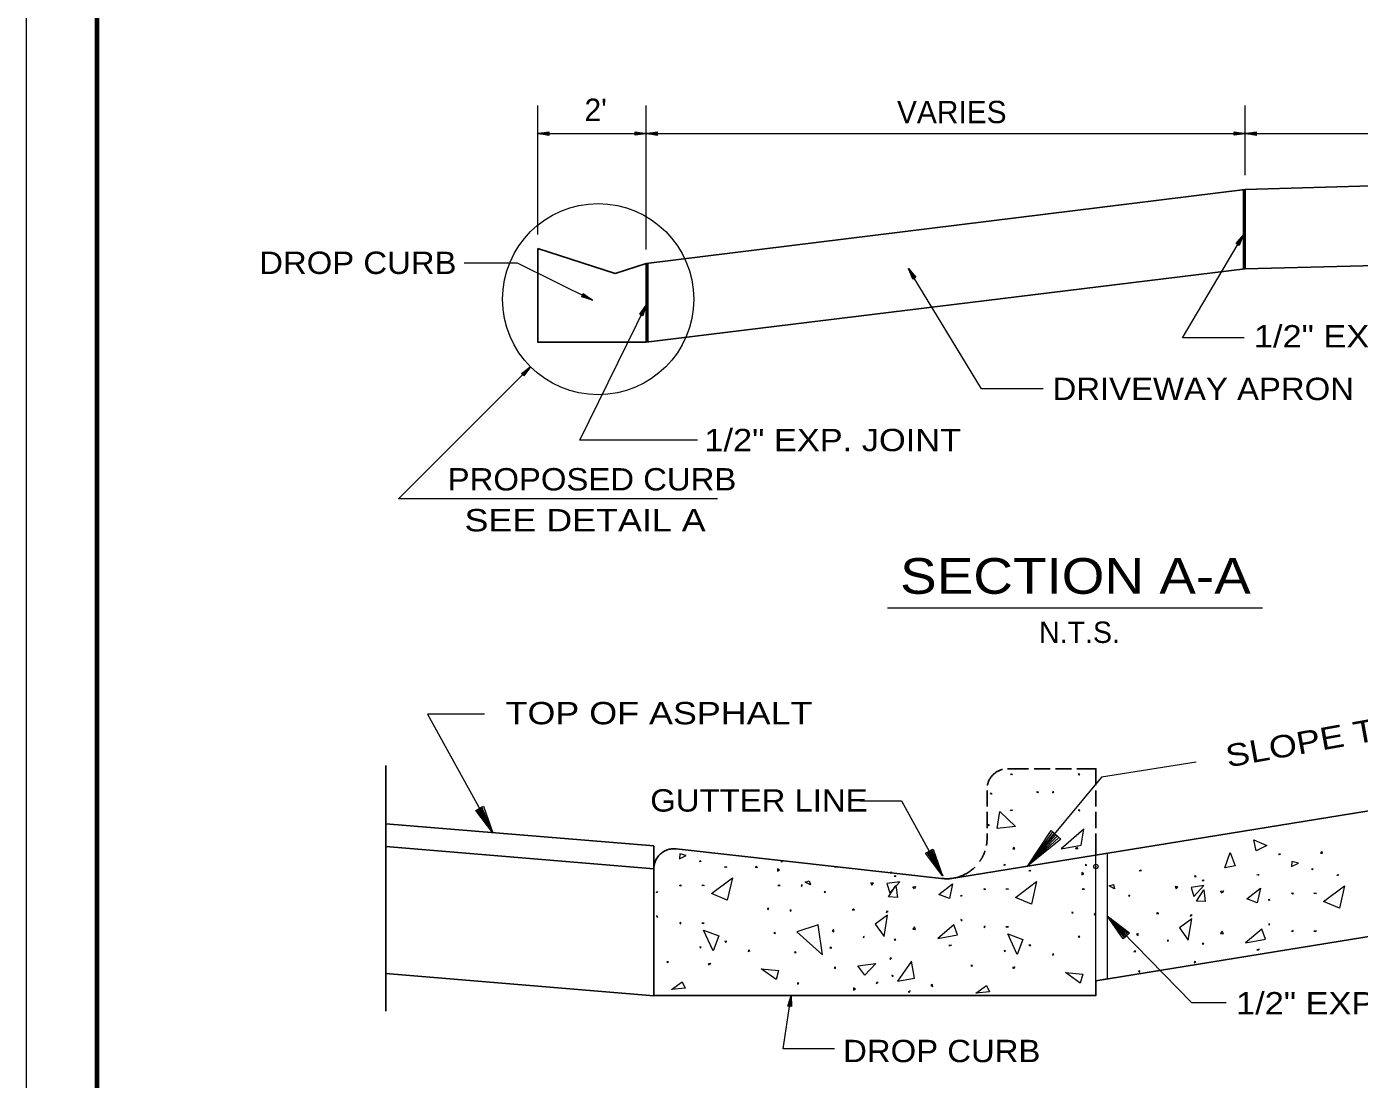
# Model space of a CAD drawing. Extents: x 124.7 to 141.7, y -6.7 to 4.3.
# Drawn here: x 124.656 to 129.626, y -4.341 to -0.415 of the extents above; entities that cross this region are included whole.
import ezdxf

# ---------------------------------------------------------------- set-up
doc = ezdxf.new("R2010")
doc.units = 0
doc.header["$LTSCALE"] = 0.033
doc.header["$PDMODE"] = 32
doc.header["$PDSIZE"] = 0.0165
for name, color, linetype, lineweight in [('6', 7, 'Continuous', 13), ('60', 7, 'Continuous', 13), ('7', 7, 'Continuous', 13), ('8', 7, 'Continuous', 13)]:
    doc.layers.add(name, color=color, linetype=linetype, lineweight=lineweight)

msp = doc.modelspace()

# ---------------------------------------------------------------- linework, layer by layer
at = {"layer": '6'}
for p, q in [((126.56211, -1.19092), (126.56211, -0.70965)), ((126.96649, -1.24615), (126.96649, -0.70965)), ((129.20005, -0.96993), (129.20005, -0.70965)), ((126.56211, -0.81446), (126.96649, -0.81446)), ((126.96649, -0.81446), (129.20005, -0.81446)), ((129.20005, -0.81446), (130.22682, -0.81446)), ((128.68544, -3.53976), (128.68564, -3.53974))]:
    msp.add_line(p, q, dxfattribs=at)
at = {"layer": '6', "lineweight": 25}
for p, q in [((129.1938, -1.31883), (129.1938, -1.0231)), ((129.20005, -1.02234), (129.20005, -1.31806)), ((126.96649, -1.29853), (126.96649, -1.59245)), ((126.97237, -1.59173), (126.97237, -1.29781)), ((125.99551, -3.17074), (125.99551, -4.08672)), ((128.09045, -3.59451), (130.92926, -3.13361)), ((128.31326, -3.18331), (128.3927, -3.18331)), ((128.4127, -3.18331), (128.4727, -3.18331)), ((128.4927, -3.18331), (128.5527, -3.18331)), ((128.23764, -3.32402), (128.23764, -3.26402)), ((128.64341, -3.26402), (128.64341, -3.32402)), ((128.23764, -3.40402), (128.23764, -3.34402)), ((128.64341, -3.34402), (128.64341, -3.40402)), ((125.99551, -3.38868), (126.99492, -3.47056)), ((128.23764, -3.44185), (128.23764, -3.42402)), ((128.64341, -3.42402), (128.64341, -3.50473)), ((125.99551, -3.47346), (126.99492, -3.55649)), ((127.07894, -3.48168), (128.09045, -3.59451)), ((128.64341, -3.97384), (131.48223, -3.51295)), ((126.99492, -4.03), (125.99551, -3.94698))]:
    msp.add_line(p, q, dxfattribs=at)
for points in [[(130.22682, -0.99256), (129.20005, -1.02234), (126.96649, -1.29853), (126.85148, -1.33557), (126.56211, -1.24331)], [(126.56211, -1.24331), (126.56211, -1.59245), (126.96649, -1.59245)], [(130.22682, -1.29244), (129.20005, -1.31806), (126.96649, -1.59245)], [(128.29489, -3.18557), (128.29205, -3.18634), (128.28925, -3.18722), (128.28648, -3.18821), (128.28375, -3.1893), (128.28106, -3.1905), (128.27844, -3.1918), (128.27585, -3.19321), (128.27332, -3.19471), (128.27086, -3.19631), (128.26846, -3.198), (128.26612, -3.19979), (128.26386, -3.20167), (128.26168, -3.20362), (128.25956, -3.20568), (128.25754, -3.2078), (128.25559, -3.21), (128.25374, -3.21228), (128.25197, -3.21462), (128.25029, -3.21704), (128.24871, -3.21952), (128.24723, -3.22206), (128.24584, -3.22465), (128.24456, -3.22729), (128.24339, -3.22999), (128.24231, -3.23273), (128.24135, -3.2355), (128.2405, -3.23831), (128.23975, -3.24116), (128.23911, -3.24402), (128.23911, -3.24402)], [(128.5727, -3.18331), (128.64341, -3.18331), (128.64341, -3.24402)], [(128.64341, -3.97384), (128.64341, -4.02829), (128.64341, -3.97384), (128.64341, -4.02829), (126.99492, -4.02829), (126.99492, -3.4723)], [(128.2351, -3.4694), (128.23527, -3.46846), (128.23544, -3.46751), (128.23559, -3.46657), (128.23575, -3.46564), (128.2359, -3.46469), (128.23604, -3.46374), (128.23618, -3.4628), (128.2363, -3.46185), (128.23643, -3.46091), (128.23654, -3.45996), (128.23666, -3.45901), (128.23676, -3.45806), (128.23686, -3.45711), (128.23696, -3.45616), (128.23704, -3.45521), (128.23712, -3.45426), (128.2372, -3.4533), (128.23727, -3.45235), (128.23733, -3.4514), (128.23739, -3.45045), (128.23744, -3.44949), (128.23748, -3.44854), (128.23752, -3.44758), (128.23755, -3.44664), (128.23758, -3.44568), (128.2376, -3.44472), (128.23761, -3.44377), (128.23763, -3.44281), (128.23764, -3.44185)], [(127.07893, -3.48168), (127.07456, -3.48131), (127.07018, -3.48121), (127.06579, -3.48135), (127.06143, -3.48176), (127.05709, -3.48242), (127.0528, -3.48332), (127.04857, -3.48447), (127.04442, -3.48586), (127.04034, -3.4875), (127.03637, -3.48936), (127.03252, -3.49146), (127.02879, -3.49378), (127.02521, -3.4963), (127.02178, -3.49903), (127.01851, -3.50196), (127.01542, -3.50506), (127.01251, -3.50834), (127.0098, -3.51179), (127.00729, -3.51539), (127.00499, -3.51912), (127.00292, -3.52299), (127.00107, -3.52697), (126.99946, -3.53104), (126.99808, -3.53521), (126.99695, -3.53945), (126.99606, -3.54374), (126.99543, -3.54808), (126.99505, -3.55245), (126.99493, -3.55683), (126.99493, -3.55683)], [(128.2096, -3.52956), (128.2105, -3.52829), (128.21139, -3.52701), (128.21226, -3.52572), (128.21311, -3.52442), (128.21396, -3.5231), (128.21479, -3.52178), (128.2156, -3.52046), (128.21641, -3.51912), (128.2172, -3.51777), (128.21797, -3.51643), (128.21874, -3.51506), (128.21948, -3.5137), (128.22022, -3.51232), (128.22094, -3.51094), (128.22164, -3.50954), (128.22233, -3.50815), (128.22301, -3.50674), (128.22367, -3.50533), (128.22431, -3.50392), (128.22495, -3.50249), (128.22556, -3.50106), (128.22617, -3.49962), (128.22675, -3.49818), (128.22732, -3.49673), (128.22789, -3.49527), (128.22843, -3.49381), (128.22896, -3.49234), (128.22947, -3.49087), (128.22997, -3.4894), (128.22997, -3.4894)], [(128.06961, -3.59218), (128.07423, -3.59261), (128.07886, -3.59292), (128.0835, -3.59308), (128.08814, -3.59309), (128.09277, -3.59297), (128.09741, -3.59271), (128.10202, -3.59229), (128.10663, -3.59175), (128.11122, -3.59105), (128.11578, -3.59022), (128.12031, -3.58925), (128.12481, -3.58815), (128.12928, -3.5869), (128.13371, -3.58551), (128.13809, -3.58399), (128.14243, -3.58234), (128.14671, -3.58055), (128.15094, -3.57865), (128.15509, -3.57659), (128.1592, -3.57443), (128.16323, -3.57214), (128.16719, -3.56972), (128.17106, -3.56718), (128.17487, -3.56452), (128.17859, -3.56175), (128.18222, -3.55886), (128.18577, -3.55587), (128.18922, -3.55277), (128.19256, -3.54956), (128.19256, -3.54956)]]:
    msp.add_lwpolyline(points, dxfattribs=at)
at = {"layer": '6'}
for points in [[(129.19658, -1.57594), (128.96645, -1.57594), (129.1938, -1.19246)], [(126.28833, -1.29674), (126.48518, -1.29674), (126.76574, -1.4354)], [(128.44665, -1.76657), (128.21744, -1.76657), (127.94499, -1.31829)], [(127.15749, -1.95719), (126.71915, -1.95719), (126.96649, -1.45435)], [(127.23191, -2.17581), (126.04357, -2.17581), (126.53531, -1.6841)], [(126.36321, -2.97942), (126.15058, -2.97942), (126.39429, -3.42135)], [(129.01684, -3.15877), (128.66483, -3.21399), (128.38959, -3.5453)], [(127.76599, -3.30291), (127.91818, -3.30291), (128.0715, -3.58106)], [(128.68564, -3.49788), (128.68564, -3.96604), (128.68524, -3.9661), (128.64386, -3.97376), (128.64341, -3.97384), (128.64341, -3.50473)], [(129.12895, -4.05633), (129.00157, -4.05633), (128.68564, -3.7322)], [(127.66917, -4.22816), (127.47782, -4.22816), (127.50725, -4.02864)]]:
    msp.add_lwpolyline(points, dxfattribs=at)
for points in [[(128.32595, -3.20594), (128.32817, -3.20165), (128.33217, -3.20439)], [(128.58309, -3.20594), (128.58087, -3.20165), (128.57689, -3.20439)], [(128.24905, -3.27661), (128.25261, -3.27334), (128.25527, -3.2774)], [(128.42225, -3.26963), (128.4268, -3.26798), (128.4277, -3.27273)], [(128.48677, -3.26963), (128.48223, -3.26798), (128.48134, -3.27273)], [(128.27578, -3.4063), (128.28531, -3.34268), (128.34415, -3.39852)], [(128.32517, -3.3403), (128.32767, -3.33617), (128.33217, -3.33798)], [(128.58388, -3.3403), (128.58136, -3.33617), (128.57689, -3.33798)], [(128.23896, -3.39156), (128.24371, -3.39067), (128.2444, -3.39545)], [(128.5141, -3.482), (128.58893, -3.46749), (128.59824, -3.40894)], [(128.33333, -3.4818), (128.34076, -3.48229), (128.33746, -3.47562)], [(128.5757, -3.4818), (128.56828, -3.48229), (128.57157, -3.47562)], [(129.24061, -3.48896), (129.23215, -3.44758), (129.28101, -3.46876)], [(127.09028, -3.51842), (127.11619, -3.50618), (127.09182, -3.49977)], [(127.16683, -3.53007), (127.16784, -3.52533), (127.1715, -3.52853)], [(127.47368, -3.53007), (127.47267, -3.52533), (127.46903, -3.52853)], [(129.1241, -3.55264), (129.14355, -3.49517), (129.16296, -3.54487)], [(129.32572, -3.50373), (129.32836, -3.49969), (129.33194, -3.50297)], [(129.48146, -3.49767), (129.48888, -3.49816), (129.48558, -3.4915)], [(127.25925, -3.55104), (127.26285, -3.54781), (127.26702, -3.55027)], [(127.38126, -3.55104), (127.37767, -3.54781), (127.37349, -3.55027)], [(127.45678, -3.56499), (127.46393, -3.56086), (127.45678, -3.55675)], [(127.67951, -3.54871), (127.67467, -3.54846), (127.67019, -3.55027)], [(127.88299, -3.57125), (127.87989, -3.56752), (127.87678, -3.57125)], [(128.30109, -3.54379), (128.3021, -3.53906), (128.30575, -3.54225)], [(128.3935, -3.56476), (128.39711, -3.56153), (128.40128, -3.56398)], [(128.59104, -3.57871), (128.59819, -3.57458), (128.59104, -3.57046)], [(128.60795, -3.54379), (128.60694, -3.53906), (128.60329, -3.54225)], [(128.81377, -3.56244), (128.80893, -3.56219), (128.80445, -3.56398)], [(129.37266, -3.54799), (129.39857, -3.53576), (129.3742, -3.52934)], [(129.44921, -3.55967), (129.45023, -3.55492), (129.45386, -3.5581)], [(129.54162, -3.58062), (129.54524, -3.5774), (129.5494, -3.57985)], [(127.09071, -3.61783), (127.09526, -3.61619), (127.09616, -3.62094)], [(127.17383, -3.61783), (127.17858, -3.61699), (127.18314, -3.6186)], [(127.20987, -3.64889), (127.28807, -3.58959), (127.26891, -3.67373)], [(127.4667, -3.61783), (127.46193, -3.61699), (127.45736, -3.6186)], [(127.54979, -3.61783), (127.54524, -3.61619), (127.54436, -3.62094)], [(127.55917, -3.60553), (127.57467, -3.6011), (127.57909, -3.61658)], [(127.81447, -3.60948), (127.80424, -3.60825), (127.80828, -3.61774)], [(127.87471, -3.64577), (127.91173, -3.60518), (127.86383, -3.6116)], [(127.87037, -3.66104), (127.89742, -3.61895), (127.903, -3.6626)], [(127.89179, -3.58496), (127.89489, -3.58124), (127.898, -3.58496)], [(127.96031, -3.62321), (127.97055, -3.62197), (127.96649, -3.63145)], [(128.05832, -3.65172), (128.10867, -3.61209), (128.09716, -3.66725)], [(128.34415, -3.6626), (128.42233, -3.60331), (128.40317, -3.68746)], [(128.69343, -3.61926), (128.70892, -3.61481), (128.71335, -3.63031)], [(128.94873, -3.62321), (128.9385, -3.62197), (128.94254, -3.63145)], [(129.00897, -3.6595), (129.04598, -3.61889), (128.99809, -3.62531)], [(129.01725, -3.58496), (129.01415, -3.58124), (129.01104, -3.58496)], [(129.03992, -3.60082), (129.04301, -3.5971), (129.04611, -3.60082)], [(129.2434, -3.5783), (129.24823, -3.57804), (129.25271, -3.57985)], [(129.49227, -3.67846), (129.57045, -3.61919), (129.55129, -3.70332)], [(127.00528, -3.64501), (127.00629, -3.64028), (127.00995, -3.64347)], [(127.63524, -3.64501), (127.63422, -3.64028), (127.63057, -3.64347)], [(128.13954, -3.65874), (128.14055, -3.65401), (128.14421, -3.6572)], [(128.22498, -3.63155), (128.22952, -3.6299), (128.23041, -3.63467)], [(128.30807, -3.63155), (128.31283, -3.63069), (128.3174, -3.63233)], [(128.60095, -3.63155), (128.59619, -3.63069), (128.59162, -3.63233)], [(128.76949, -3.65874), (128.76848, -3.65401), (128.76482, -3.6572)], [(129.01849, -3.67692), (129.04553, -3.63481), (129.0511, -3.67846)], [(129.10843, -3.63908), (129.11867, -3.63784), (129.11462, -3.64731)], [(129.20644, -3.66758), (129.25681, -3.62797), (129.24527, -3.68312)], [(129.28766, -3.67461), (129.28868, -3.66986), (129.29231, -3.67305)], [(129.3731, -3.64742), (129.37765, -3.64577), (129.37853, -3.65054)], [(129.45621, -3.64742), (129.46096, -3.64656), (129.46552, -3.6482)], [(127.42398, -3.70479), (127.41921, -3.70392), (127.42009, -3.70868)], [(127.50786, -3.71179), (127.50371, -3.70931), (127.5032, -3.71412)], [(127.7432, -3.70946), (127.73911, -3.70683), (127.73465, -3.70868)], [(127.86824, -3.71568), (127.86354, -3.71451), (127.86124, -3.71877)], [(128.55824, -3.71852), (128.55348, -3.71764), (128.55435, -3.72241)], [(128.64212, -3.72551), (128.63797, -3.72302), (128.63746, -3.72783)], [(128.87746, -3.72319), (128.87339, -3.72055), (128.86891, -3.72241)], [(127.00528, -3.73201), (127.00629, -3.73675), (127.00995, -3.73355)], [(127.09071, -3.75919), (127.09526, -3.76084), (127.09616, -3.75608)], [(127.17383, -3.75919), (127.17858, -3.76005), (127.18314, -3.75842)], [(127.52817, -3.79149), (127.62447, -3.87689), (127.60786, -3.76492)], [(127.86687, -3.7295), (127.8204, -3.76271), (127.85359, -3.8092)], [(127.96031, -3.78127), (127.97055, -3.78249), (127.96649, -3.77302)], [(128.05365, -3.81628), (128.12732, -3.80271), (128.11342, -3.76536)], [(128.13954, -3.74572), (128.14055, -3.75047), (128.14421, -3.74728)], [(128.22498, -3.77292), (128.22952, -3.77456), (128.23041, -3.76981)], [(128.30807, -3.77292), (128.31283, -3.77377), (128.3174, -3.77212)], [(129.00113, -3.74321), (128.95465, -3.77643), (128.98785, -3.82291)], [(129.00249, -3.72939), (128.99779, -3.72824), (128.9955, -3.7325)], [(129.28766, -3.76159), (129.28868, -3.76632), (129.29231, -3.76314)], [(127.1806, -3.78484), (127.23706, -3.80586), (127.21603, -3.86232)], [(127.25925, -3.82599), (127.26285, -3.82923), (127.26702, -3.82675)], [(127.44883, -3.79723), (127.4466, -3.79293), (127.44262, -3.79567)], [(127.66617, -3.79064), (127.66664, -3.78321), (127.65999, -3.78652)], [(127.77814, -3.81353), (127.77984, -3.809), (127.77503, -3.80965)], [(127.89179, -3.8195), (127.89489, -3.82323), (127.898, -3.8195)], [(128.31486, -3.79855), (128.37132, -3.81959), (128.35028, -3.87605)], [(128.58309, -3.81094), (128.58087, -3.80665), (128.57689, -3.80939)], [(128.80043, -3.80436), (128.8009, -3.79694), (128.79424, -3.80024)], [(128.9124, -3.82725), (128.91408, -3.82271), (128.90929, -3.82336)], [(129.10843, -3.79712), (129.11867, -3.79836), (129.11462, -3.78887)], [(129.20176, -3.83215), (129.27546, -3.81857), (129.26154, -3.78122)], [(129.3731, -3.78878), (129.37765, -3.79044), (129.37853, -3.78567)], [(129.45621, -3.78878), (129.46096, -3.78963), (129.46552, -3.78799)], [(127.16683, -3.84696), (127.16784, -3.85169), (127.1715, -3.8485)], [(127.35252, -3.86092), (127.34798, -3.85926), (127.34708, -3.86402)], [(127.52572, -3.8679), (127.52216, -3.86462), (127.51951, -3.86867)], [(127.65853, -3.85081), (127.65436, -3.84835), (127.65077, -3.85158)], [(128.09527, -3.84203), (128.1001, -3.84229), (128.10459, -3.84048)], [(128.30109, -3.86067), (128.3021, -3.86542), (128.30575, -3.86222)], [(128.3935, -3.83971), (128.39711, -3.84294), (128.40128, -3.84048)], [(128.48677, -3.87462), (128.48223, -3.87298), (128.48134, -3.87773)], [(128.79279, -3.86453), (128.78862, -3.86207), (128.78503, -3.86531)], [(129.03992, -3.83537), (129.04301, -3.83908), (129.04611, -3.83537)], [(129.2434, -3.8579), (129.24823, -3.85817), (129.25271, -3.85635)], [(127.04333, -3.90287), (127.04599, -3.90693), (127.04955, -3.90366)], [(127.19907, -3.90894), (127.2065, -3.90846), (127.20319, -3.91512)], [(127.67251, -3.92771), (127.6726, -3.92285), (127.66784, -3.92382)], [(127.7551, -3.9176), (127.82273, -3.90994), (127.78151, -3.95333)], [(127.88144, -3.88965), (127.87682, -3.88819), (127.87522, -3.89275)], [(127.90312, -3.97566), (127.96731, -3.9646), (127.95624, -3.9004)], [(128.17759, -3.9166), (128.18024, -3.92065), (128.18381, -3.91736)], [(128.33333, -3.92267), (128.34076, -3.92218), (128.33746, -3.92883)], [(129.0157, -3.90336), (129.01108, -3.9019), (129.00948, -3.90647)], [(127.39534, -3.92873), (127.46009, -3.93527), (127.45069, -3.96858)], [(127.88247, -3.95309), (127.88434, -3.95756), (127.88869, -3.95544)], [(128.5296, -3.94246), (128.59435, -3.94898), (128.58495, -3.9823)], [(128.80677, -3.94143), (128.80686, -3.93658), (128.8021, -3.93754)], [(127.06107, -4.00623), (127.10104, -3.97827), (127.11199, -4.00179)], [(127.53582, -3.98284), (127.53107, -3.98194), (127.53039, -3.98673)], [(127.74708, -4.00382), (127.73954, -4.00009), (127.74008, -4.00848)], [(127.83096, -3.98051), (127.82614, -3.98006), (127.82397, -3.9844)], [(127.94383, -4.01523), (127.94865, -4.01568), (127.95081, -4.01133)], [(128.02771, -3.99193), (128.03524, -3.99565), (128.0347, -3.98726)], [(128.19533, -4.01994), (128.23529, -3.99198), (128.24624, -4.01552)]]:
    msp.add_lwpolyline(points, close=True, dxfattribs=at)
msp.add_circle((126.78739, -1.43201), 0.35651, dxfattribs=at)
msp.add_point((128.64341, -3.54736), dxfattribs=at)
at = {"layer": '60'}
msp.add_lwpolyline([(141.66697, -6.70846), (124.65648, -6.70846), (124.65648, 4.29833), (141.66697, 4.29833)], close=True, dxfattribs=at)
at = {"layer": '60', "lineweight": 70}
msp.add_lwpolyline([(140.98583, 4.08146), (124.91782, 4.08146), (124.91782, -6.47409), (140.98583, -6.47409)], close=True, dxfattribs=at)
at = {"layer": '7'}
msp.add_line((127.86658, -2.58312), (129.2651, -2.58312), dxfattribs=at)
at = {"layer": '8'}
for points in [[(126.60326, -0.81035), (126.56159, -0.81452), (126.60326, -0.81452), (126.60326, -0.8166), (126.56159, -0.81452), (126.60326, -0.81869), (126.60326, -0.81244), (126.56368, -0.81452)], [(126.5618, -0.81425), (126.60329, -0.80829), (126.60329, -0.82119), (126.56166, -0.8144)], [(126.9668, -0.81467), (126.92531, -0.82062), (126.92531, -0.80773), (126.96695, -0.81452)], [(126.92534, -0.81856), (126.96701, -0.8144), (126.92534, -0.8144), (126.92534, -0.81231), (126.96701, -0.8144), (126.92534, -0.81023), (126.92534, -0.81648), (126.96493, -0.8144)], [(127.00764, -0.81035), (126.96597, -0.81452), (127.00764, -0.81452), (127.00764, -0.8166), (126.96597, -0.81452), (127.00764, -0.81869), (127.00764, -0.81244), (126.96805, -0.81452)], [(126.96618, -0.81425), (127.00767, -0.80829), (127.00767, -0.82119), (126.96603, -0.8144)], [(129.20036, -0.81467), (129.15887, -0.82062), (129.15887, -0.80773), (129.20051, -0.81452)], [(129.15891, -0.81856), (129.20057, -0.8144), (129.15891, -0.8144), (129.15891, -0.81231), (129.20057, -0.8144), (129.15891, -0.81023), (129.15891, -0.81648), (129.19849, -0.8144)], [(129.2412, -0.81035), (129.19953, -0.81452), (129.2412, -0.81452), (129.2412, -0.8166), (129.19953, -0.81452), (129.2412, -0.81869), (129.2412, -0.81244), (129.20161, -0.81452)], [(129.19974, -0.81425), (129.24123, -0.80829), (129.24123, -0.82119), (129.19959, -0.8144)], [(129.19415, -1.1923), (129.17811, -1.23103), (129.16702, -1.22445), (129.19409, -1.1921)], [(129.17635, -1.22995), (129.19402, -1.19198), (129.17277, -1.22782), (129.17098, -1.22676), (129.19402, -1.19198), (129.16919, -1.2257), (129.17456, -1.22889), (129.19296, -1.19377)], [(127.96988, -1.35132), (127.94467, -1.31789), (127.96631, -1.35349), (127.96453, -1.35457), (127.94467, -1.31789), (127.96275, -1.35566), (127.96809, -1.35241), (127.94575, -1.31967)], [(127.94501, -1.31792), (127.97165, -1.35028), (127.96062, -1.35698), (127.94481, -1.31787)], [(126.76593, -1.43573), (126.72609, -1.42269), (126.73181, -1.41112), (126.76613, -1.43566)], [(126.72704, -1.42085), (126.76624, -1.43557), (126.72889, -1.41711), (126.7298, -1.41525), (126.76624, -1.43557), (126.73073, -1.41338), (126.72796, -1.41898), (126.76438, -1.43466)], [(126.96682, -1.45417), (126.95385, -1.49403), (126.94228, -1.48833), (126.96675, -1.45398)], [(126.95201, -1.49309), (126.96667, -1.45386), (126.94827, -1.49125), (126.94641, -1.49033), (126.96667, -1.45386), (126.94454, -1.48942), (126.95015, -1.49217), (126.96575, -1.45573)], [(126.53569, -1.68403), (126.51056, -1.71758), (126.50144, -1.70847), (126.53569, -1.68383)], [(126.50912, -1.7161), (126.53564, -1.6837), (126.50618, -1.71316), (126.50471, -1.71169), (126.53564, -1.6837), (126.50323, -1.71021), (126.50765, -1.71464), (126.53417, -1.68517)], [(126.39422, -3.42229), (126.33108, -3.33866), (126.35931, -3.32308), (126.39471, -3.42244)], [(126.33564, -3.33623), (126.39506, -3.42242), (126.34476, -3.33121), (126.34932, -3.32869), (126.39506, -3.42242), (126.35389, -3.32618), (126.3402, -3.33372), (126.39254, -3.41785)], [(128.38954, -3.54453), (128.47619, -3.41339), (128.51233, -3.44551), (128.38959, -3.5453)], [(128.4819, -3.41861), (128.38978, -3.54579), (128.49357, -3.42899), (128.49941, -3.43418), (128.38978, -3.54579), (128.50525, -3.43936), (128.48773, -3.4238), (128.39497, -3.53995)], [(128.07142, -3.58199), (128.00828, -3.49835), (128.03652, -3.48279), (128.07192, -3.58214)], [(128.01284, -3.49594), (128.07226, -3.58213), (128.02196, -3.49091), (128.02652, -3.4884), (128.07226, -3.58213), (128.03108, -3.48588), (128.0174, -3.49343), (128.06975, -3.57756)], [(128.76478, -3.7987), (128.68461, -3.73137), (128.75732, -3.80597), (128.75359, -3.8096), (128.68461, -3.73137), (128.74986, -3.81324), (128.76105, -3.80233), (128.68825, -3.7351)], [(128.68547, -3.73128), (128.76853, -3.79516), (128.74545, -3.81766), (128.68495, -3.73127)], [(127.50749, -4.02835), (127.50793, -4.07027), (127.49515, -4.06856), (127.50736, -4.02819)], [(127.50589, -4.06997), (127.50725, -4.02811), (127.50176, -4.06942), (127.49969, -4.06915), (127.50725, -4.02811), (127.49762, -4.06886), (127.50382, -4.06969), (127.50698, -4.03018)]]:
    msp.add_lwpolyline(points, dxfattribs=at)

# ---------------------------------------------------------------- texts
at = {"layer": '6'}
for s, height, p in [("2'", 0.08333, (126.73656, -0.7673)), ('VARIES', 0.08333, (127.90166, -0.77546)), ('N.T.S.', 0.07965, (128.43121, -2.71383))]:
    msp.add_text(s, height=height, dxfattribs=at).set_placement(p)
for s, width, p in [('DROP CURB', 1.1, (125.52371, -1.33786)), ('1/2" EXP. JOINT', 1.15, (129.23241, -1.61189)), ('DRIVEWAY APRON', 1.1, (128.48178, -1.80811)), ('1/2" EXP. JOINT', 1.15, (127.18358, -1.99873)), ('PROPOSED CURB', 1.1, (126.22651, -2.14521)), ('SEE DETAIL A', 1.2, (126.28921, -2.29775)), ('TOP OF ASPHALT', 1.2, (126.44223, -3.0173)), ('GUTTER LINE', 1.1, (126.98164, -3.34285)), ('1/2" EXP. JOINT', 1.15, (129.16601, -4.09927)), ('DROP CURB', 1.1, (127.70091, -4.27728))]:
    msp.add_text(s, height=0.08333, dxfattribs=dict(at, width=width)).set_placement(p)
at = {"layer": '6', "width": 1.2}
msp.add_text('SLOPE TO MATCH D.W.', height=0.08333, rotation=10.26, dxfattribs=at).set_placement((129.13573, -3.1782))
at = {"layer": '7', "width": 1.15}
msp.add_text('SECTION A-A', height=0.1331, dxfattribs=at).set_placement((127.9132, -2.53061))

doc.saveas('drawing.dxf')
